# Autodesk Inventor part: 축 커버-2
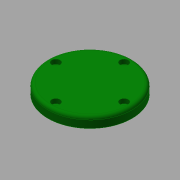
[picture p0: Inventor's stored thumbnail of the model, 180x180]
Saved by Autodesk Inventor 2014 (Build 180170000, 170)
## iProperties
Created: 2015-10
Part Number: 축 커버-2
Document SubType Name: Modeling
Designer: mdu
Density: 7.86 g/cm^3
Material: 강철, 연강
Appearance: 진녹색
Mass: 403.237 g
Surface Area: 134.748 cm^2
Volume: 51.3024 cm^3
Author: mdu
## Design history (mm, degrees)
sketch "스케치1"
  geometry: C1 r 40 at (0, 0) reference; C2 r 26 at (0, 0) reference; 1 further point
  node "참조1"
  node "참조2"
extrude "돌출1" new body sketch "스케치1" distance "d0" = 10; taper "d1" = 0 deg
extrude "돌출2" join sketch "스케치1" distance "d2" = 3; taper "d3" = 0 deg
sketch "스케치2"
  geometry: C1 r 20 at (0, 0); 1 further point
  constraints: 1 centre point, 1 coincident
  dimensions: "d13" = 40 diameter of C1
extrude "돌출3" cut sketch "스케치2" distance "d14" = 3; taper "d15" = 0 deg
sketch "스케치3"
  geometry: C1 r 1.621 at (0, 32.5) reference; 1 further point
hole "구멍2" sketch "스케치3" at (0, 32.5) diameter "d16" = 4.5; stored, may be unused: countersink angle "d20" = 90 deg, drill point angle "d22" = 118 deg; dims "d17" = 6, "d18" = 8, "d19" = 4.4, "d21" = 8
fillet "모깎기1" dims "d26" = 3, "d27" = 0.3
chamfer "모따기1" distance "d28" = 1; stored, may be unused: second distance "d29" = 2, angle "d30" = 45 deg
node "솔리드1"
pattern_circular "원형 패턴1" dims angle "d24" = 360 deg
node "참조3"
